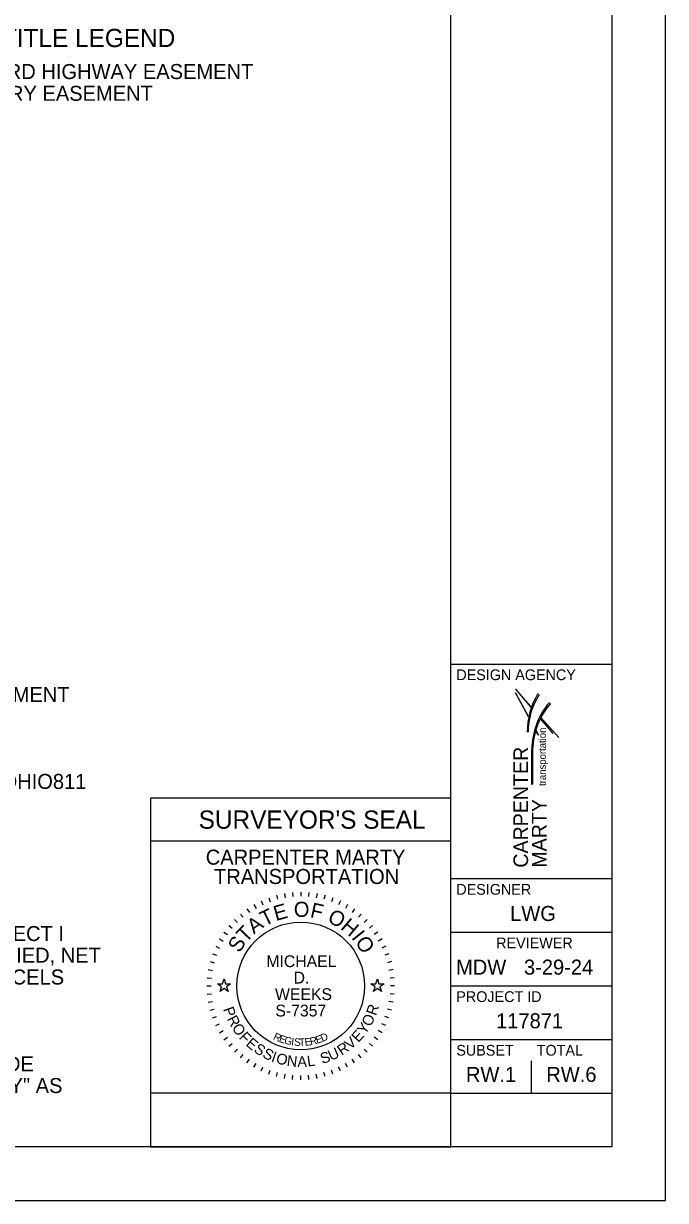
# Model space of a CAD drawing. Extents: x 0 to 34, y 0 to 22.
# Drawn here: x 28.02 to 34, y 0 to 10.97 of the extents above; entities that cross this region are included whole.
import ezdxf

# ---------------------------------------------------------------- set-up
doc = ezdxf.new("R2010")
doc.units = 0
for name, color, linetype in [('Default', 7, 'Continuous'), ('SH_Border', 7, 'Continuous'), ('SH_Cut_Line', 7, 'Continuous'), ('SH_Data', 7, 'Continuous'), ('SH_Text', 7, 'Continuous')]:
    doc.layers.add(name, color=color, linetype=linetype)

msp = doc.modelspace()

# ---------------------------------------------------------------- linework, layer by layer
at = {"layer": 'Default'}
for points in [[(29.824, 2.02), (29.871, 2.02), (29.885, 2.065), (29.899, 2.02), (29.946, 2.02), (29.908, 1.992), (29.923, 1.948), (29.885, 1.975), (29.847, 1.948), (29.862, 1.992)], [(31.254, 2.02), (31.301, 2.02), (31.315, 2.065), (31.329, 2.02), (31.376, 2.02), (31.338, 1.992), (31.353, 1.948), (31.315, 1.975), (31.277, 1.948), (31.292, 1.992)]]:
    msp.add_lwpolyline(points, close=True, dxfattribs=at)
at = {"layer": 'SH_Border'}
for p, q in [((32, 0.5), (32, 21.5)), ((32, 5), (33.5, 5)), ((32, 3), (33.5, 3)), ((32, 2.5), (33.5, 2.5)), ((32, 2), (33.5, 2)), ((32, 1.5), (33.5, 1.5)), ((32, 1), (33.5, 1))]:
    msp.add_line(p, q, dxfattribs=at)
msp.add_lwpolyline([(1.5, 21.5), (33.5, 21.5), (33.5, 0.5), (1.5, 0.5)], close=True, dxfattribs=at)
at = {"layer": 'SH_Cut_Line'}
msp.add_lwpolyline([(0, 0), (34, 0), (34, 22), (0, 22)], close=True, dxfattribs=at)
at = {"layer": 'SH_Data'}
for p, q in [((32.75, 4), (32.75, 4)), ((32, 3.75), (29.2, 3.75)), ((29.2, 3.75), (29.2, 0.5)), ((32, 0.5), (32, 3.75)), ((32, 3.35), (29.2, 3.35)), ((30.448, 2.862), (30.455, 2.822)), ((30.524, 2.872), (30.527, 2.832)), ((30.6, 2.875), (30.6, 2.835)), ((30.676, 2.872), (30.673, 2.832)), ((30.752, 2.862), (30.745, 2.822)), ((30.163, 2.758), (30.183, 2.723)), ((30.23, 2.793), (30.247, 2.757)), ((30.301, 2.822), (30.314, 2.785)), ((30.374, 2.845), (30.384, 2.807)), ((30.826, 2.845), (30.816, 2.807)), ((30.899, 2.822), (30.886, 2.785)), ((30.97, 2.793), (30.953, 2.757)), ((31.037, 2.758), (31.017, 2.723)), ((30.038, 2.67), (30.063, 2.64)), ((30.098, 2.717), (30.121, 2.684)), ((31.102, 2.717), (31.079, 2.684)), ((31.162, 2.67), (31.137, 2.64)), ((29.93, 2.562), (29.96, 2.537)), ((29.981, 2.619), (30.01, 2.59)), ((31.219, 2.619), (31.19, 2.59)), ((31.27, 2.562), (31.24, 2.537)), ((29.842, 2.438), (29.877, 2.418)), ((29.883, 2.502), (29.916, 2.479)), ((31.317, 2.502), (31.284, 2.479)), ((31.358, 2.438), (31.323, 2.418)), ((29.807, 2.37), (29.843, 2.353)), ((31.393, 2.37), (31.357, 2.353)), ((29.755, 2.226), (29.793, 2.216)), ((29.778, 2.299), (29.815, 2.286)), ((31.422, 2.299), (31.385, 2.286)), ((31.445, 2.226), (31.407, 2.216)), ((29.738, 2.152), (29.778, 2.145)), ((31.462, 2.152), (31.422, 2.145)), ((29.725, 2), (29.765, 2)), ((29.728, 2.076), (29.768, 2.073)), ((31.472, 2.076), (31.432, 2.073)), ((31.475, 2), (31.435, 2)), ((29.728, 1.924), (29.768, 1.927)), ((31.472, 1.924), (31.432, 1.927)), ((29.738, 1.848), (29.778, 1.855)), ((29.755, 1.774), (29.793, 1.784)), ((31.445, 1.774), (31.407, 1.784)), ((31.462, 1.848), (31.422, 1.855)), ((29.778, 1.701), (29.815, 1.714)), ((29.807, 1.63), (29.843, 1.647)), ((31.393, 1.63), (31.357, 1.647)), ((31.422, 1.701), (31.385, 1.714)), ((29.842, 1.563), (29.877, 1.583)), ((31.358, 1.563), (31.323, 1.583)), ((29.883, 1.498), (29.916, 1.521)), ((29.93, 1.438), (29.96, 1.463)), ((31.27, 1.438), (31.24, 1.463)), ((31.317, 1.498), (31.284, 1.521)), ((29.981, 1.381), (30.01, 1.41)), ((30.038, 1.33), (30.063, 1.36)), ((31.162, 1.33), (31.137, 1.36)), ((31.219, 1.381), (31.19, 1.41)), ((30.098, 1.283), (30.121, 1.316)), ((30.163, 1.242), (30.183, 1.277)), ((30.23, 1.207), (30.247, 1.243)), ((30.301, 1.178), (30.314, 1.215)), ((30.899, 1.178), (30.886, 1.215)), ((30.97, 1.207), (30.953, 1.243)), ((31.037, 1.242), (31.017, 1.277)), ((31.102, 1.283), (31.079, 1.316)), ((32.75, 1), (32.75, 1.3)), ((30.374, 1.155), (30.384, 1.193)), ((30.448, 1.138), (30.455, 1.178)), ((30.524, 1.128), (30.527, 1.168)), ((30.6, 1.125), (30.6, 1.165)), ((30.676, 1.128), (30.673, 1.168)), ((30.752, 1.138), (30.745, 1.178)), ((30.826, 1.155), (30.816, 1.193)), ((32, 0.5), (29.2, 0.5))]:
    msp.add_line(p, q, dxfattribs=at)
msp.add_lwpolyline([(32, 0.5), (32, 1), (29.2, 1), (29.2, 0.5)], close=True, dxfattribs=at)
msp.add_circle((30.6, 2), 0.595, dxfattribs=at)
at = {"layer": 'SH_Text'}
for p, q in [((32.721, 4.516), (32.602, 4.732)), ((32.839, 4.502), (33.006, 4.316)), ((32.952, 4.353), (32.834, 4.491)), ((32.811, 4.34), (32.79, 4.38)), ((32.82, 4.334), (32.791, 4.386)), ((32.755, 3.878), (32.755, 4.204)), ((32.762, 3.878), (32.762, 4.204))]:
    msp.add_line(p, q, dxfattribs=at)
for points in [[(32.746, 4.604), (32.601, 4.766)], [(32.601, 4.766), (32.744, 4.598)], [(32.721, 4.516), (32.602, 4.732)], [(32.602, 4.732), (32.719, 4.511)]]:
    msp.add_lwpolyline(points, dxfattribs=at)
for centre, radius, start, end in [((33.432, 4.36), 0.721, 149.5704, 179.5529), ((33.373, 4.362), 0.654, 147.1423, 179.6525), ((33.426, 4.204), 0.671, 139.2898, 180.0106), ((33.433, 4.188), 0.672, 138.5126, 178.6075)]:
    msp.add_arc(centre, radius, start, end, dxfattribs=at)

# ---------------------------------------------------------------- texts
at = {"layer": 'SH_Data'}
for s, height, p in [('DESIGN AGENCY', 0.1, (32.05, 4.85)), ("SURVEYOR'S SEAL", 0.17, (29.648, 3.465)), ('CARPENTER MARTY', 0.14, (29.714, 3.13)), ('TRANSPORTATION', 0.14, (29.791, 2.95)), ('DESIGNER', 0.1, (32.05, 2.85)), ('LWG', 0.14, (32.552, 2.605)), ('REVIEWER', 0.1, (32.422, 2.35)), ('MICHAEL', 0.11, (30.279, 2.175)), ('  MDW', 0.14, (31.944, 2.105)), ('3-29-24', 0.14, (32.681, 2.105)), ('D.', 0.11, (30.533, 2.022)), ('WEEKS', 0.11, (30.36, 1.868)), ('PROJECT ID', 0.1, (32.05, 1.85)), ('S-7357', 0.11, (30.363, 1.715)), ('117871', 0.14, (32.421, 1.605)), ('SUBSET', 0.1, (32.05, 1.35)), ('TOTAL', 0.1, (32.8, 1.35)), ('RW.1', 0.14, (32.14, 1.105)), ('RW.6', 0.14, (32.889, 1.105))]:
    msp.add_text(s, height=height, dxfattribs=at).set_placement(p)
for s, height, rotation, p in [('E', 0.14, 15.7571, (30.368, 2.604)), ('O', 0.14, 359.7812, (30.535, 2.644)), ('F', 0.14, 347.4362, (30.681, 2.642)), ('A', 0.14, 36.4747, (30.163, 2.478)), ('T', 0.14, 25.7167, (30.262, 2.552)), ('O', 0.14, 332.2586, (30.84, 2.602)), ('H', 0.14, 319.9136, (30.963, 2.536)), ('T', 0.14, 46.4344, (30.088, 2.396)), ('S', 0.14, 57.1924, (30.028, 2.301)), ('I', 0.14, 308.367, (31.066, 2.448)), ('O', 0.14, 303.1491, (31.102, 2.409)), ('P', 0.1, 289.7431, (29.875, 1.784)), ('R', 0.1, 70.983, (31.301, 1.717)), ('R', 0.1, 296.9802, (29.909, 1.693)), ('Y', 0.1, 55.5058, (31.2, 1.54)), ('O', 0.1, 62.7428, (31.25, 1.613)), ('O', 0.1, 304.7158, (29.953, 1.608)), ('F', 0.1, 312.956, (30.019, 1.516)), ('R', 0.07, 334.487, (30.337, 1.505)), ('E', 0.07, 341.04, (30.391, 1.48)), ('E', 0.07, 17.6836, (30.75, 1.46)), ('D', 0.07, 23.3052, (30.801, 1.477)), ('E', 0.1, 48.2687, (31.137, 1.467)), ('E', 0.1, 319.6885, (30.081, 1.45)), ('S', 0.1, 326.9255, (30.155, 1.389)), ('G', 0.07, 347.4752, (30.441, 1.462)), ('I', 0.07, 353.7858, (30.509, 1.447)), ('S', 0.07, 356.8926, (30.536, 1.443)), ('T', 0.07, 3.0061, (30.586, 1.439)), ('E', 0.07, 6.0117, (30.639, 1.441)), ('R', 0.07, 11.9184, (30.692, 1.447)), ('R', 0.1, 33.296, (30.981, 1.347)), ('V', 0.1, 41.0316, (31.061, 1.401)), ('S', 0.1, 334.1626, (30.236, 1.337)), ('I', 0.1, 341.3997, (30.319, 1.298)), ('O', 0.1, 345.1351, (30.362, 1.282)), ('N', 0.1, 353.3752, (30.466, 1.255)), ('A', 0.1, 1.1108, (30.569, 1.244)), ('L', 0.1, 8.3479, (30.666, 1.247)), ('S', 0.1, 18.3234, (30.8, 1.271)), ('U', 0.1, 25.5604, (30.883, 1.299))]:
    msp.add_text(s, height=height, rotation=rotation, dxfattribs=at).set_placement(p)
at = {"layer": 'SH_Text'}
for s, height, p in [('TYPES OF TITLE LEGEND', 0.17, (26.626, 10.751)), ('SH = STANDARD HIGHWAY EASEMENT', 0.14, (26.626, 10.453)), ('T = TEMPORARY EASEMENT', 0.14, (26.626, 10.25))]:
    msp.add_text(s, height=height, dxfattribs=at).set_placement(p)
for s, height, rotation, p in [('I, MICHAEL D. WEEKS, P.S., HAVE CONDUCTED A SURVEY OF THE EXISTING CONDITIONS FOR THE OHIO DEPARTMENT ', 0.14, 360, (17.533, 4.646)), ('transportation', 0.06649, 90, (32.885, 3.864)), ('CARPENTER ', 0.1367, 90, (32.719, 3.102)), ('BELIEVED TO BE ACCURATE, THEIR LOCATION IS AS MARKED ON THE GROUND BY THE UTILITY COMPANY PER OHIO811 ', 0.14, 360, (17.533, 3.836)), ('MARTY', 0.1367, 90, (32.891, 3.102)), ('CENTERLINE OF EXISTING RIGHT OF WAY FOR PROPERTY TAKES CONTAINED HEREIN. AS A PART OF THIS PROJECT I ', 0.14, 360, (17.533, 2.418)), ('HAVE ESTABLISHED THE PROPOSED PROPERTY LINES, CALCULATED THE GROSS TAKE, PRESENT ROAD OCCUPIED, NET ', 0.14, 360, (17.533, 2.216)), ('TAKE AND NET RESIDUE; AS WELL AS PREPARED THE LEGAL DESCRIPTIONS NECESSARY TO ACQUIRE THE PARCELS ', 0.14, 360, (17.533, 2.013)), ('ALL OF MY WORK CONTAINED HEREIN WAS CONDUCTED IN ACCORDANCE WITH THE OHIO ADMINISTRATIVE CODE ', 0.14, 360, (17.533, 1.203)), ('CHAPTER 4733-37 STANDARDS FOR  BOUNDARY SURVEYS, UNLESS NOTED OTHERWISE. THE WORDS "I" AND "MY" AS ', 0.14, 360, (17.533, 1.001))]:
    msp.add_text(s, height=height, rotation=rotation, dxfattribs=at).set_placement(p)

doc.saveas('drawing.dxf')
